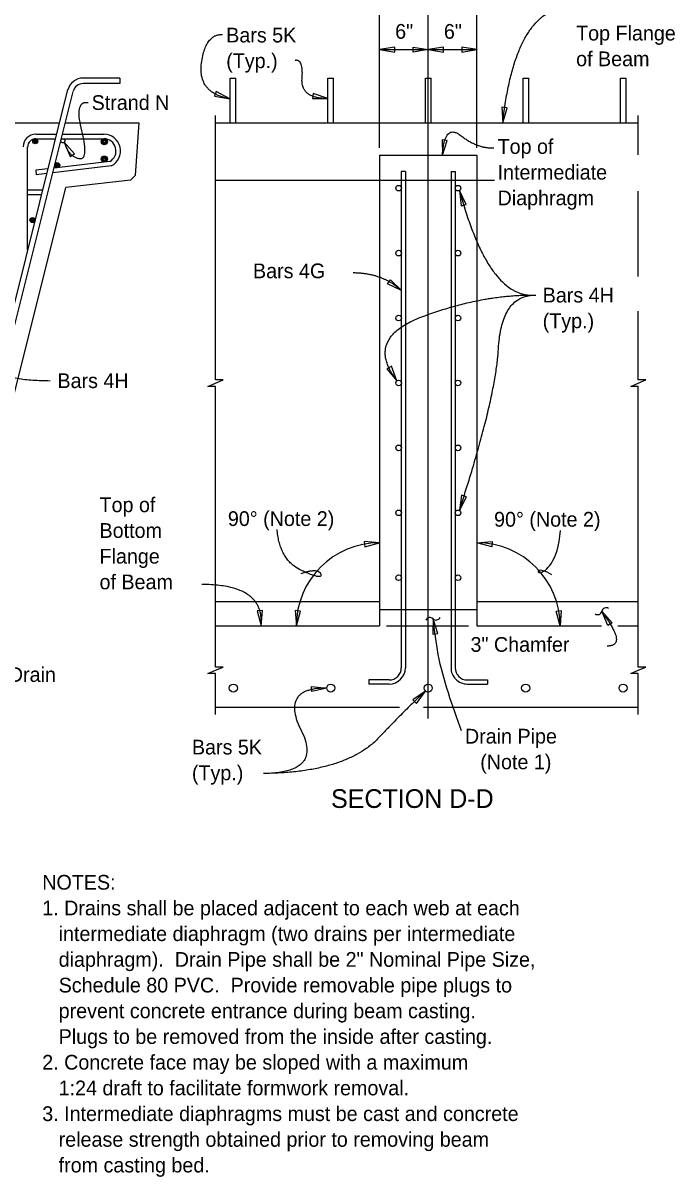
# Model space of a CAD drawing. Extents: x 120693.4 to 120747.1, y 120647.1 to 120670.1.
# Drawn here: x 120702.1 to 120708.79, y 120649.89 to 120661.74 of the extents above; entities that cross this region are included whole.
import ezdxf

# ---------------------------------------------------------------- set-up
doc = ezdxf.new("R2010")
doc.units = 0
for name, color, linetype in [('BeamConc', 7, 'Continuous'), ('BeamConc_h', 7, 'Continuous'), ('CL_Major', 7, 'Continuous'), ('Dimension', 7, 'Continuous'), ('Miscellaneous', 7, 'Continuous'), ('Rebar', 7, 'Continuous'), ('TextStructures', 7, 'Continuous')]:
    doc.layers.add(name, color=color, linetype=linetype)

msp = doc.modelspace()

# ---------------------------------------------------------------- linework, layer by layer
at = {"layer": 'BeamConc'}
for p, q in [((120701.956, 120660.718), (120702.475, 120660.718)), ((120702.534, 120660.718), (120703.289, 120660.718)), ((120703.289, 120660.718), (120703.251, 120660.175)), ((120704.077, 120660.718), (120708.414, 120660.718)), ((120705.759, 120660.384), (120705.759, 120655.551)), ((120705.759, 120660.384), (120706.759, 120660.384)), ((120706.759, 120660.384), (120706.759, 120655.551)), ((120703.205, 120660.129), (120702.539, 120660.051)), ((120703.205, 120660.129), (120703.251, 120660.175)), ((120701.228, 120654.806), (120702.539, 120660.051)), ((120704.077, 120655.801), (120705.759, 120655.801)), ((120706.759, 120655.801), (120708.414, 120655.801)), ((120704.077, 120655.551), (120705.759, 120655.551)), ((120706.759, 120655.551), (120708.036, 120655.551)), ((120708.206, 120655.551), (120708.414, 120655.551)), ((120704.077, 120654.718), (120705.964, 120654.718)), ((120706.211, 120654.718), (120708.414, 120654.718))]:
    msp.add_line(p, q, dxfattribs=at)
at = {"layer": 'BeamConc_h'}
for p, q in [((120704.077, 120660.129), (120706.938, 120660.129)), ((120705.832, 120655.551), (120706.674, 120655.551))]:
    msp.add_line(p, q, dxfattribs=at)
at = {"layer": 'CL_Major'}
msp.add_line((120706.259, 120654.599), (120706.259, 120662.164), dxfattribs=at)
at = {"layer": 'Dimension'}
for p, q in [((120705.759, 120660.46), (120705.759, 120662.293)), ((120706.759, 120660.46), (120706.759, 120662.293)), ((120705.759, 120661.468), (120706.759, 120661.468))]:
    msp.add_line(p, q, dxfattribs=at)
for points in [[(120705.759, 120661.468), (120705.916, 120661.441), (120705.916, 120661.494)], [(120706.259, 120661.468), (120706.103, 120661.441), (120706.103, 120661.494)], [(120706.259, 120661.468), (120706.416, 120661.441), (120706.416, 120661.494)], [(120706.759, 120661.468), (120706.603, 120661.494), (120706.603, 120661.441)], [(120704.223, 120660.964), (120704.084, 120661.04), (120704.067, 120660.99)], [(120705.228, 120660.965), (120705.079, 120661.018), (120705.07, 120660.965)], [(120707.024, 120660.718), (120707.068, 120660.87), (120707.016, 120660.876)], [(120702.524, 120660.517), (120702.583, 120660.37), (120702.628, 120660.398)], [(120706.405, 120660.384), (120706.455, 120660.534), (120706.403, 120660.543)], [(120706.581, 120660.022), (120706.597, 120659.865), (120706.648, 120659.879)], [(120705.984, 120658.995), (120705.84, 120659.062), (120705.871, 120659.106)], [(120705.938, 120658.069), (120705.882, 120658.217), (120705.836, 120658.191)], [(120706.579, 120656.737), (120706.653, 120656.877), (120706.602, 120656.894)], [(120705.759, 120656.405), (120705.602, 120656.417), (120705.607, 120656.364)], [(120706.759, 120656.405), (120706.917, 120656.417), (120706.912, 120656.364)], [(120704.544, 120655.551), (120704.558, 120655.709), (120704.505, 120655.705)], [(120704.906, 120655.551), (120704.947, 120655.704), (120704.893, 120655.709)], [(120706.31, 120655.625), (120706.306, 120655.466), (120706.358, 120655.474)], [(120707.613, 120655.551), (120707.572, 120655.704), (120707.625, 120655.709)], [(120708.04, 120655.702), (120708.146, 120655.584), (120708.101, 120655.556)], [(120705.218, 120654.912), (120705.064, 120654.876), (120705.061, 120654.928)], [(120706.232, 120654.882), (120706.101, 120654.793), (120706.138, 120654.755)]]:
    msp.add_lwpolyline(points, close=True, dxfattribs=at)
for points in [[(120704.077, 120655.551), (120704.077, 120658.01), (120703.999, 120658.01), (120704.077, 120658.044), (120704.154, 120658.077), (120704.077, 120658.077), (120704.077, 120660.793)], [(120708.414, 120660.388), (120708.414, 120660.793)], [(120708.414, 120659.138), (120708.414, 120660.016)], [(120708.414, 120655.551), (120708.414, 120658.01), (120708.337, 120658.01), (120708.414, 120658.044), (120708.492, 120658.077), (120708.414, 120658.077), (120708.414, 120658.782)], [(120704.077, 120654.642), (120704.077, 120655.062), (120703.999, 120655.062), (120704.077, 120655.096), (120704.154, 120655.129), (120704.077, 120655.129), (120704.077, 120655.551)], [(120708.414, 120654.642), (120708.414, 120655.062), (120708.337, 120655.062), (120708.414, 120655.096), (120708.492, 120655.129), (120708.414, 120655.129), (120708.414, 120655.551)]]:
    msp.add_lwpolyline(points, dxfattribs=at)
for centre, radius, start, end in [((120705.759, 120655.551), 0.854, 90, 180), ((120706.759, 120655.551), 0.854, 0, 90), ((120708.084, 120655.693), 0.0447, 56.5869, 168.3141), ((120706.277, 120655.593), 0.0447, 44.1793, 155.9065), ((120706.341, 120655.656), 0.0447, 224.1793, 335.9065), ((120707.996, 120655.711), 0.0447, 236.5869, 348.3141)]:
    msp.add_arc(centre, radius, start, end, dxfattribs=at)
for points, degree in [([(120707.024, 120660.718), (120707.154, 120661.882), (120707.703, 120661.908)], 2), ([(120704.223, 120660.963), (120703.894, 120661.023), (120703.97, 120661.627), (120704.147, 120661.624)], 2), ([(120705.228, 120660.965), (120704.948, 120660.968), (120704.981, 120661.37), (120704.895, 120661.358)], 2), ([(120702.524, 120660.517), (120702.567, 120660.373), (120702.781, 120660.327), (120702.626, 120660.952), (120702.771, 120660.924)], 2), ([(120706.405, 120660.384), (120706.425, 120660.718), (120706.766, 120660.451), (120706.932, 120660.46)], 2), ([(120706.581, 120660.022), (120706.881, 120658.901), (120707.362, 120658.948)], 2), ([(120701.137, 120659.981), (120700.774, 120658.069), (120702.378, 120658.069)], 2), ([(120705.983, 120658.996), (120705.787, 120659.174), (120705.49, 120659.175)], 2), ([(120705.938, 120658.069), (120705.601, 120658.506), (120706.818, 120658.956), (120707.362, 120658.948)], 2), ([(120706.579, 120656.737), (120706.951, 120657.872), (120707.011, 120658.947), (120707.362, 120658.948)], 2), ([(120704.955, 120656.09), (120705.131, 120656.151), (120705.182, 120656.016), (120704.734, 120656.224), (120704.708, 120656.542)], 2), ([(120707.528, 120656.077), (120707.381, 120656.168), (120707.337, 120656.016), (120707.589, 120656.201), (120707.618, 120656.531)], 3), ([(120704.543, 120655.551), (120704.584, 120655.976), (120703.937, 120655.976)], 2), ([(120708.064, 120655.663), (120708.3, 120655.344), (120708.095, 120655.344)], 2), ([(120705.218, 120654.912), (120704.734, 120654.915), (120705.177, 120654.04), (120704.567, 120654.035)], 2), ([(120706.232, 120654.882), (120706.085, 120654.752), (120705.41, 120654.045), (120704.567, 120654.035)], 2)]:
    msp.add_open_spline(points, degree=degree, dxfattribs=at)
msp.add_spline([(120706.602, 120654.473), (120706.362, 120655.259), (120706.31, 120655.625)], degree=3, dxfattribs=at)
at = {"layer": 'Miscellaneous'}
msp.add_line((120705.759, 120655.718), (120706.759, 120655.718), dxfattribs=at)
at = {"layer": 'Rebar'}
for p, q in [((120703.095, 120661.176), (120702.717, 120661.176)), ((120703.095, 120661.119), (120702.717, 120661.119)), ((120703.095, 120661.176), (120703.095, 120661.119)), ((120704.228, 120660.718), (120704.228, 120661.176)), ((120704.228, 120661.176), (120704.286, 120661.176)), ((120704.286, 120660.718), (120704.286, 120661.176)), ((120705.228, 120660.718), (120705.228, 120661.176)), ((120705.228, 120661.176), (120705.286, 120661.176)), ((120705.286, 120660.718), (120705.286, 120661.176)), ((120706.231, 120660.718), (120706.231, 120661.176)), ((120706.231, 120661.176), (120706.288, 120661.176)), ((120706.288, 120660.718), (120706.288, 120661.176)), ((120707.233, 120660.718), (120707.233, 120661.176)), ((120707.233, 120661.176), (120707.291, 120661.176)), ((120707.291, 120660.718), (120707.291, 120661.176)), ((120708.233, 120660.718), (120708.233, 120661.176)), ((120708.233, 120661.176), (120708.291, 120661.176)), ((120708.291, 120660.718), (120708.291, 120661.176)), ((120701.051, 120655.021), (120702.56, 120661.059)), ((120701.106, 120655.007), (120702.615, 120661.04)), ((120702.232, 120660.6), (120702.446, 120660.6)), ((120702.505, 120660.6), (120702.935, 120660.6)), ((120702.232, 120660.553), (120702.434, 120660.553)), ((120702.493, 120660.553), (120702.935, 120660.553)), ((120702.148, 120659.411), (120702.148, 120660.47)), ((120702.357, 120660.245), (120702.232, 120660.23)), ((120703.006, 120660.274), (120702.406, 120660.203)), ((120702.992, 120660.319), (120702.418, 120660.252)), ((120702.232, 120660.23), (120702.237, 120660.183)), ((120702.345, 120660.196), (120702.237, 120660.183)), ((120705.983, 120660.218), (120705.983, 120655.121)), ((120706.025, 120660.218), (120705.983, 120660.218)), ((120706.025, 120660.218), (120706.025, 120655.119)), ((120706.494, 120660.218), (120706.494, 120655.119)), ((120706.494, 120660.218), (120706.535, 120660.218)), ((120706.535, 120660.218), (120706.535, 120655.121)), ((120702.148, 120660.028), (120702.303, 120660.028)), ((120702.148, 120659.981), (120702.291, 120659.981)), ((120705.65, 120654.996), (120705.65, 120654.954)), ((120705.858, 120654.996), (120705.65, 120654.996)), ((120705.858, 120654.954), (120705.65, 120654.954)), ((120706.66, 120654.996), (120706.869, 120654.996)), ((120706.66, 120654.954), (120706.869, 120654.954)), ((120706.869, 120654.996), (120706.869, 120654.954))]:
    msp.add_line(p, q, dxfattribs=at)
for centre, radius in [((120702.227, 120660.527), 0.026), ((120702.227, 120660.527), 0.0188), ((120702.227, 120660.527), 0.0106), ((120702.227, 120660.527), 0.00453), ((120702.509, 120660.532), 0.0208), ((120702.935, 120660.522), 0.0312), ((120702.935, 120660.522), 0.0225), ((120702.935, 120660.522), 0.0121), ((120702.935, 120660.344), 0.0312), ((120702.935, 120660.344), 0.0216), ((120702.935, 120660.344), 0.0111), ((120702.452, 120660.282), 0.026), ((120702.452, 120660.282), 0.0188), ((120702.452, 120660.282), 0.0106), ((120702.452, 120660.282), 0.00453), ((120705.955, 120660.046), 0.0287), ((120706.564, 120660.046), 0.0287), ((120702.198, 120659.718), 0.026), ((120702.198, 120659.718), 0.0188), ((120702.198, 120659.718), 0.0106), ((120702.198, 120659.718), 0.00453), ((120705.955, 120659.379), 0.0287), ((120706.564, 120659.379), 0.0287), ((120705.955, 120658.712), 0.0287), ((120706.564, 120658.712), 0.0287), ((120705.955, 120658.046), 0.0287), ((120706.564, 120658.046), 0.0287), ((120705.955, 120657.379), 0.0287), ((120706.564, 120657.379), 0.0287), ((120705.955, 120656.712), 0.0287), ((120706.564, 120656.712), 0.0287), ((120705.955, 120656.046), 0.0287), ((120706.564, 120656.046), 0.0287), ((120704.259, 120654.913), 0.0413), ((120705.259, 120654.913), 0.0413), ((120706.259, 120654.913), 0.0413), ((120707.259, 120654.913), 0.0413), ((120708.259, 120654.913), 0.0413)]:
    msp.add_circle(centre, radius, dxfattribs=at)
for centre, radius, start, end in [((120702.717, 120661.015), 0.161, 90, 165.9638), ((120702.717, 120661.015), 0.104, 90, 165.9638), ((120702.232, 120660.47), 0.13, 90, 180), ((120702.93, 120660.428), 0.172, 296.336, 90), ((120702.232, 120660.47), 0.0833, 90, 180), ((120702.93, 120660.428), 0.125, 299.7664, 90), ((120705.858, 120655.121), 0.125, 270, 0), ((120705.858, 120655.121), 0.167, 270, 360), ((120706.66, 120655.121), 0.167, 179.24, 270), ((120706.66, 120655.121), 0.125, 180, 270)]:
    msp.add_arc(centre, radius, start, end, dxfattribs=at)

# ---------------------------------------------------------------- texts
at = {"layer": 'Dimension'}
for s, p in [('Bars 5K', (120704.186, 120661.542)), ('Top Flange', (120707.777, 120661.562)), ('(Typ.)', (120704.186, 120661.278)), ('of Beam', (120707.777, 120661.298)), ('Top of', (120706.971, 120660.398)), ('Intermediate', (120706.971, 120660.134)), ('Diaphragm', (120706.971, 120659.87)), ('Bars 4H', (120707.434, 120658.872)), ('(Typ.)', (120707.434, 120658.608)), ('Top of', (120702.886, 120656.719)), ('Bottom', (120702.886, 120656.455)), ('Flange', (120702.886, 120656.191)), ('of Beam', (120702.886, 120655.927)), ('Pipe Drain', (120701.494, 120654.976)), ('Drain Pipe', (120706.636, 120654.343)), ('Bars 5K', (120703.834, 120654.231)), ('(Note 1)', (120706.793, 120654.079)), ('(Typ.)', (120703.834, 120653.967))]:
    msp.add_text(s, height=0.1512, dxfattribs=at).set_placement(p)
at = {"layer": 'TextStructures'}
for s, height, p in [('6"', 0.1512, (120705.92, 120661.58)), ('6"', 0.1512, (120706.42, 120661.58)), ('Strand N', 0.1512, (120702.805, 120660.849)), ('Bars 4G', 0.1512, (120704.461, 120659.121)), ('Bars 4H', 0.1512, (120702.454, 120657.993)), ('90° (Note 2)', 0.1512, (120704.203, 120656.577)), ('90° (Note 2)', 0.1512, (120706.935, 120656.57)), ('3" Chamfer', 0.1512, (120706.693, 120655.285)), ('SECTION D-D', 0.192, (120705.262, 120653.682)), ('NOTES:', 0.1512, (120702.298, 120652.843)), ('1. Drains shall be placed adjacent to each web at each', 0.1512, (120702.298, 120652.579)), ('   intermediate diaphragm (two drains per intermediate ', 0.1512, (120702.298, 120652.315)), ('   diaphragm).  Drain Pipe shall be 2" Nominal Pipe Size, ', 0.1512, (120702.298, 120652.051)), ('   Schedule 80 PVC.  Provide removable pipe plugs to', 0.1512, (120702.298, 120651.787)), ('   prevent concrete entrance during beam casting.', 0.1512, (120702.298, 120651.523)), ('   Plugs to be removed from the inside after casting.', 0.1512, (120702.298, 120651.259)), ('2. Concrete face may be sloped with a maximum', 0.1512, (120702.298, 120650.995)), ('   1:24 draft to facilitate formwork removal.', 0.1512, (120702.298, 120650.731)), ('3. Intermediate diaphragms must be cast and concrete', 0.1512, (120702.298, 120650.467)), ('   release strength obtained prior to removing beam', 0.1512, (120702.298, 120650.203)), ('   from casting bed.', 0.1512, (120702.298, 120649.939))]:
    msp.add_text(s, height=height, dxfattribs=at).set_placement(p)

doc.saveas('drawing.dxf')
